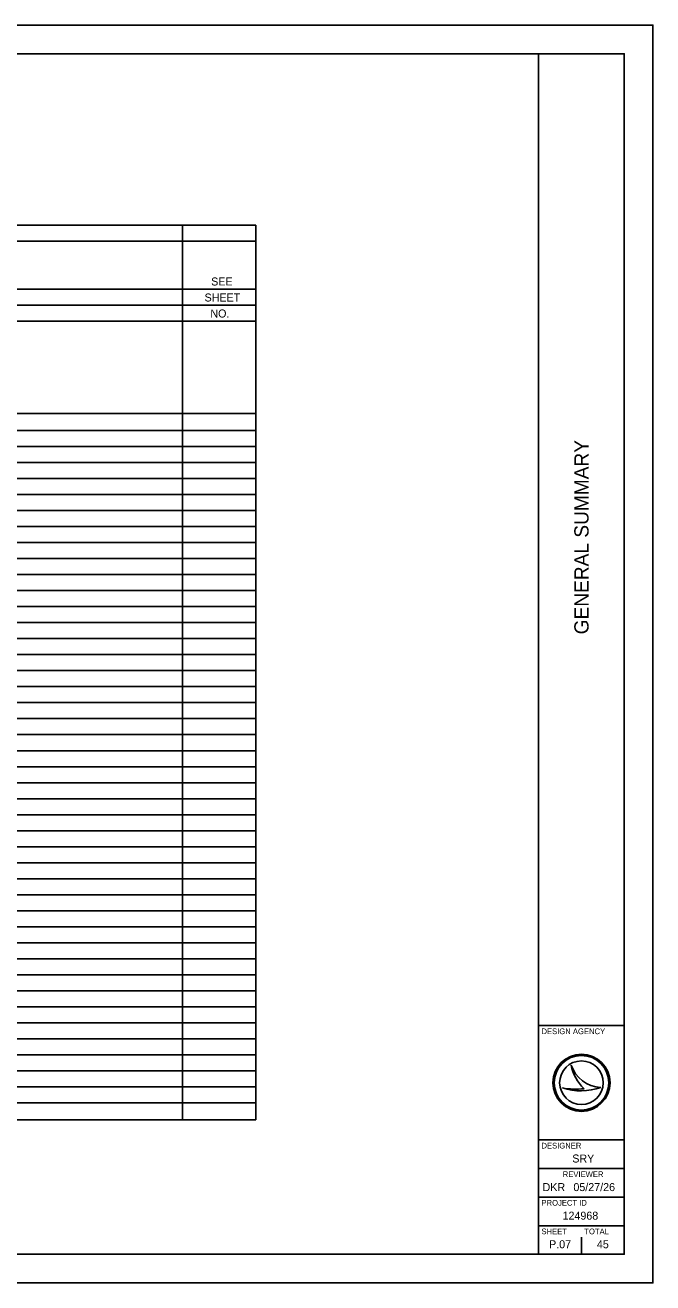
# Model space of a CAD drawing. Extents: x 0 to 34, y 0 to 22.
# Drawn here: x 23.01 to 34, y 0 to 22 of the extents above; entities that cross this region are included whole.
import ezdxf

# ---------------------------------------------------------------- set-up
doc = ezdxf.new("R2010")
doc.units = 0
for name, color, linetype in [('SH_Border', 7, 'Continuous'), ('SH_Cut_Line', 7, 'Continuous'), ('SH_Data', 7, 'Continuous'), ('SH_Text', 7, 'Continuous')]:
    doc.layers.add(name, color=color, linetype=linetype)

msp = doc.modelspace()

# ---------------------------------------------------------------- linework, layer by layer
at = {"layer": 'SH_Border'}
for p, q in [((32, 0.5), (32, 21.5)), ((32, 4.5), (33.5, 4.5)), ((32, 2.5), (33.5, 2.5)), ((32, 2), (33.5, 2)), ((32, 1.5), (33.5, 1.5)), ((32, 1), (33.5, 1))]:
    msp.add_line(p, q, dxfattribs=at)
msp.add_lwpolyline([(1.5, 21.5), (33.5, 21.5), (33.5, 0.5), (1.5, 0.5)], close=True, dxfattribs=at)
at = {"layer": 'SH_Cut_Line'}
msp.add_lwpolyline([(0, 0), (34, 0), (34, 22), (0, 22)], close=True, dxfattribs=at)
at = {"layer": 'SH_Data'}
for p, q in [((6, 18.5), (27.049, 18.5)), ((25.765, 18.5), (25.765, 2.853)), ((27.049, 18.5), (27.049, 2.853)), ((6, 14.909), (27.049, 14.909)), ((6, 14.629), (27.049, 14.629)), ((6, 14.349), (27.049, 14.349)), ((6, 14.069), (27.049, 14.069)), ((6, 13.789), (27.049, 13.789)), ((6, 13.509), (27.049, 13.509)), ((6, 13.229), (27.049, 13.229)), ((6, 12.949), (27.049, 12.949)), ((6, 12.669), (27.049, 12.669)), ((6, 12.389), (27.049, 12.389)), ((6, 12.109), (27.049, 12.109)), ((6, 11.829), (27.049, 11.829)), ((6, 11.549), (27.049, 11.549)), ((6, 11.269), (27.049, 11.269)), ((6, 10.989), (27.049, 10.989)), ((6, 10.709), (27.049, 10.709)), ((6, 10.429), (27.049, 10.429)), ((6, 10.149), (27.049, 10.149)), ((6, 9.869), (27.049, 9.869)), ((6, 9.589), (27.049, 9.589)), ((6, 9.309), (27.049, 9.309)), ((6, 9.029), (27.049, 9.029)), ((6, 8.749), (27.049, 8.749)), ((6, 8.469), (27.049, 8.469)), ((6, 8.189), (27.049, 8.189)), ((6, 7.909), (27.049, 7.909)), ((6, 7.629), (27.049, 7.629)), ((6, 7.349), (27.049, 7.349)), ((6, 7.069), (27.049, 7.069)), ((6, 6.789), (27.049, 6.789)), ((6, 6.509), (27.049, 6.509)), ((6, 6.229), (27.049, 6.229)), ((6, 5.949), (27.049, 5.949)), ((6, 5.669), (27.049, 5.669)), ((6, 5.389), (27.049, 5.389)), ((6, 5.109), (27.049, 5.109)), ((6, 4.829), (27.049, 4.829)), ((6, 4.549), (27.049, 4.549)), ((6, 4.269), (27.049, 4.269)), ((6, 3.989), (27.049, 3.989)), ((32.567, 3.81), (32.567, 3.81)), ((6, 3.709), (27.049, 3.709)), ((6, 3.429), (27.049, 3.429)), ((32.417, 3.41), (32.417, 3.41)), ((32.75, 3.5), (32.75, 3.5)), ((33.087, 3.419), (33.087, 3.419)), ((6, 3.149), (27.049, 3.149)), ((6, 2.853), (27.049, 2.853)), ((32.375, 0.675), (32.375, 0.675)), ((32.75, 0.5), (32.75, 0.8))]:
    msp.add_line(p, q, dxfattribs=at)
for radius in [0.5, 0.477, 0.477, 0.382]:
    msp.add_circle((32.75, 3.5), radius, dxfattribs=at)
for centre, radius, start, end in [((33.116, 3.998), 0.58, 198.9257, 198.9319), ((33.347, 3.97), 0.796, 191.6379, 191.6421), ((33.116, 3.998), 0.58, 198.9319, 267.1657), ((33.347, 3.97), 0.796, 191.6421, 226.0947), ((32.739, 4.37), 1.013, 251.4576, 290.0832), ((32.648, 4.654), 1.266, 259.4964, 259.4995), ((32.739, 4.37), 1.013, 251.4527, 251.4576), ((32.648, 4.654), 1.266, 259.4995, 276.6672)]:
    msp.add_arc(centre, radius, start, end, dxfattribs=at)
at = {"layer": 'SH_Text'}
for points in [[(16.492, 18.5), (25.765, 18.5), (25.765, 18.22), (16.492, 18.22)], [(25.765, 18.5), (27.049, 18.5), (27.049, 18.22), (25.765, 18.22)], [(16.492, 18.22), (25.765, 18.22), (25.765, 17.38), (16.492, 17.38)], [(25.765, 18.22), (27.049, 18.22), (27.049, 17.38), (25.765, 17.38)], [(16.492, 17.38), (25.765, 17.38), (25.765, 17.1), (16.492, 17.1)], [(25.765, 17.38), (27.049, 17.38), (27.049, 17.1), (25.765, 17.1)], [(16.492, 17.1), (25.765, 17.1), (25.765, 16.82), (16.492, 16.82)], [(25.765, 17.1), (27.049, 17.1), (27.049, 16.82), (25.765, 16.82)], [(16.492, 16.82), (25.765, 16.82), (25.765, 15.206), (16.492, 15.206)], [(25.765, 16.82), (27.049, 16.82), (27.049, 15.206), (25.765, 15.206)], [(16.492, 14.909), (25.765, 14.909), (25.765, 14.629), (16.492, 14.629)], [(25.765, 14.909), (27.049, 14.909), (27.049, 14.629), (25.765, 14.629)], [(16.492, 14.629), (25.765, 14.629), (25.765, 14.349), (16.492, 14.349)], [(25.765, 14.629), (27.049, 14.629), (27.049, 14.349), (25.765, 14.349)], [(16.492, 14.349), (25.765, 14.349), (25.765, 14.069), (16.492, 14.069)], [(25.765, 14.349), (27.049, 14.349), (27.049, 14.069), (25.765, 14.069)], [(16.492, 14.069), (25.765, 14.069), (25.765, 13.789), (16.492, 13.789)], [(25.765, 14.069), (27.049, 14.069), (27.049, 13.789), (25.765, 13.789)], [(16.492, 13.789), (25.765, 13.789), (25.765, 13.509), (16.492, 13.509)], [(25.765, 13.789), (27.049, 13.789), (27.049, 13.509), (25.765, 13.509)], [(16.492, 13.509), (25.765, 13.509), (25.765, 13.229), (16.492, 13.229)], [(25.765, 13.509), (27.049, 13.509), (27.049, 13.229), (25.765, 13.229)], [(16.492, 13.229), (25.765, 13.229), (25.765, 12.949), (16.492, 12.949)], [(25.765, 13.229), (27.049, 13.229), (27.049, 12.949), (25.765, 12.949)], [(16.492, 12.949), (25.765, 12.949), (25.765, 12.669), (16.492, 12.669)], [(25.765, 12.949), (27.049, 12.949), (27.049, 12.669), (25.765, 12.669)], [(16.492, 12.669), (25.765, 12.669), (25.765, 12.389), (16.492, 12.389)], [(25.765, 12.669), (27.049, 12.669), (27.049, 12.389), (25.765, 12.389)], [(16.492, 12.389), (25.765, 12.389), (25.765, 12.109), (16.492, 12.109)], [(25.765, 12.389), (27.049, 12.389), (27.049, 12.109), (25.765, 12.109)], [(16.492, 12.109), (25.765, 12.109), (25.765, 11.829), (16.492, 11.829)], [(25.765, 12.109), (27.049, 12.109), (27.049, 11.829), (25.765, 11.829)], [(16.492, 11.829), (25.765, 11.829), (25.765, 11.549), (16.492, 11.549)], [(25.765, 11.829), (27.049, 11.829), (27.049, 11.549), (25.765, 11.549)], [(16.492, 11.549), (25.765, 11.549), (25.765, 11.269), (16.492, 11.269)], [(25.765, 11.549), (27.049, 11.549), (27.049, 11.269), (25.765, 11.269)], [(16.492, 11.269), (25.765, 11.269), (25.765, 10.989), (16.492, 10.989)], [(25.765, 11.269), (27.049, 11.269), (27.049, 10.989), (25.765, 10.989)], [(16.492, 10.989), (25.765, 10.989), (25.765, 10.709), (16.492, 10.709)], [(25.765, 10.989), (27.049, 10.989), (27.049, 10.709), (25.765, 10.709)], [(16.492, 10.709), (25.765, 10.709), (25.765, 10.429), (16.492, 10.429)], [(25.765, 10.709), (27.049, 10.709), (27.049, 10.429), (25.765, 10.429)], [(16.492, 10.429), (25.765, 10.429), (25.765, 10.149), (16.492, 10.149)], [(25.765, 10.429), (27.049, 10.429), (27.049, 10.149), (25.765, 10.149)], [(16.492, 10.149), (25.765, 10.149), (25.765, 9.869), (16.492, 9.869)], [(25.765, 10.149), (27.049, 10.149), (27.049, 9.869), (25.765, 9.869)], [(16.492, 9.869), (25.765, 9.869), (25.765, 9.589), (16.492, 9.589)], [(25.765, 9.869), (27.049, 9.869), (27.049, 9.589), (25.765, 9.589)], [(16.492, 9.589), (25.765, 9.589), (25.765, 9.309), (16.492, 9.309)], [(25.765, 9.589), (27.049, 9.589), (27.049, 9.309), (25.765, 9.309)], [(16.492, 9.309), (25.765, 9.309), (25.765, 9.029), (16.492, 9.029)], [(25.765, 9.309), (27.049, 9.309), (27.049, 9.029), (25.765, 9.029)], [(16.492, 9.029), (25.765, 9.029), (25.765, 8.749), (16.492, 8.749)], [(25.765, 9.029), (27.049, 9.029), (27.049, 8.749), (25.765, 8.749)], [(16.492, 8.749), (25.765, 8.749), (25.765, 8.469), (16.492, 8.469)], [(25.765, 8.749), (27.049, 8.749), (27.049, 8.469), (25.765, 8.469)], [(16.492, 8.469), (25.765, 8.469), (25.765, 8.189), (16.492, 8.189)], [(25.765, 8.469), (27.049, 8.469), (27.049, 8.189), (25.765, 8.189)], [(16.492, 8.189), (25.765, 8.189), (25.765, 7.909), (16.492, 7.909)], [(25.765, 8.189), (27.049, 8.189), (27.049, 7.909), (25.765, 7.909)], [(16.492, 7.909), (25.765, 7.909), (25.765, 7.629), (16.492, 7.629)], [(25.765, 7.909), (27.049, 7.909), (27.049, 7.629), (25.765, 7.629)], [(16.492, 7.629), (25.765, 7.629), (25.765, 7.349), (16.492, 7.349)], [(25.765, 7.629), (27.049, 7.629), (27.049, 7.349), (25.765, 7.349)], [(16.492, 7.349), (25.765, 7.349), (25.765, 7.069), (16.492, 7.069)], [(25.765, 7.349), (27.049, 7.349), (27.049, 7.069), (25.765, 7.069)], [(16.492, 7.069), (25.765, 7.069), (25.765, 6.789), (16.492, 6.789)], [(25.765, 7.069), (27.049, 7.069), (27.049, 6.789), (25.765, 6.789)], [(16.492, 6.789), (25.765, 6.789), (25.765, 6.509), (16.492, 6.509)], [(25.765, 6.789), (27.049, 6.789), (27.049, 6.509), (25.765, 6.509)], [(16.492, 6.509), (25.765, 6.509), (25.765, 6.229), (16.492, 6.229)], [(25.765, 6.509), (27.049, 6.509), (27.049, 6.229), (25.765, 6.229)], [(16.492, 6.229), (25.765, 6.229), (25.765, 5.949), (16.492, 5.949)], [(25.765, 6.229), (27.049, 6.229), (27.049, 5.949), (25.765, 5.949)], [(16.492, 5.949), (25.765, 5.949), (25.765, 5.669), (16.492, 5.669)], [(25.765, 5.949), (27.049, 5.949), (27.049, 5.669), (25.765, 5.669)], [(16.492, 5.669), (25.765, 5.669), (25.765, 5.389), (16.492, 5.389)], [(25.765, 5.669), (27.049, 5.669), (27.049, 5.389), (25.765, 5.389)], [(16.492, 5.389), (25.765, 5.389), (25.765, 5.109), (16.492, 5.109)], [(25.765, 5.389), (27.049, 5.389), (27.049, 5.109), (25.765, 5.109)], [(16.492, 5.109), (25.765, 5.109), (25.765, 4.829), (16.492, 4.829)], [(25.765, 5.109), (27.049, 5.109), (27.049, 4.829), (25.765, 4.829)], [(16.492, 4.829), (25.765, 4.829), (25.765, 4.549), (16.492, 4.549)], [(25.765, 4.829), (27.049, 4.829), (27.049, 4.549), (25.765, 4.549)], [(16.492, 4.549), (25.765, 4.549), (25.765, 4.269), (16.492, 4.269)], [(25.765, 4.549), (27.049, 4.549), (27.049, 4.269), (25.765, 4.269)], [(16.492, 4.269), (25.765, 4.269), (25.765, 3.989), (16.492, 3.989)], [(25.765, 4.269), (27.049, 4.269), (27.049, 3.989), (25.765, 3.989)], [(16.492, 3.989), (25.765, 3.989), (25.765, 3.709), (16.492, 3.709)], [(25.765, 3.989), (27.049, 3.989), (27.049, 3.709), (25.765, 3.709)], [(16.492, 3.709), (25.765, 3.709), (25.765, 3.429), (16.492, 3.429)], [(25.765, 3.709), (27.049, 3.709), (27.049, 3.429), (25.765, 3.429)], [(16.492, 3.429), (25.765, 3.429), (25.765, 3.149), (16.492, 3.149)], [(25.765, 3.429), (27.049, 3.429), (27.049, 3.149), (25.765, 3.149)], [(16.492, 3.149), (25.765, 3.149), (25.765, 2.853), (16.492, 2.853)], [(25.765, 3.149), (27.049, 3.149), (27.049, 2.853), (25.765, 2.853)]]:
    msp.add_lwpolyline(points, close=True, dxfattribs=at)

# ---------------------------------------------------------------- texts
at = {"layer": 'SH_Data'}
msp.add_text('GENERAL SUMMARY', height=0.25, rotation=90, dxfattribs=at).set_placement((32.875, 11.344))
for s, height, p in [('DESIGN AGENCY', 0.1, (32.05, 4.35)), ('DESIGNER', 0.1, (32.05, 2.35)), ('SRY', 0.14, (32.589, 2.105)), ('REVIEWER', 0.1, (32.422, 1.85)), ('DKR', 0.14, (32.069, 1.605)), ('05/27/26', 0.14, (32.609, 1.605)), ('PROJECT ID', 0.1, (32.05, 1.35)), ('124968', 0.14, (32.419, 1.105)), ('SHEET', 0.1, (32.05, 0.85)), ('TOTAL', 0.1, (32.8, 0.85)), ('P.07', 0.14, (32.183, 0.605)), ('45', 0.14, (33.02, 0.605))]:
    msp.add_text(s, height=height, dxfattribs=at).set_placement(p)
at = {"layer": 'SH_Text'}
for s, p in [('SEE', (26.268, 17.446)), ('SHEET', (26.152, 17.166)), ('NO.', (26.254, 16.886))]:
    msp.add_text(s, height=0.14, dxfattribs=at).set_placement(p)

doc.saveas('drawing.dxf')
